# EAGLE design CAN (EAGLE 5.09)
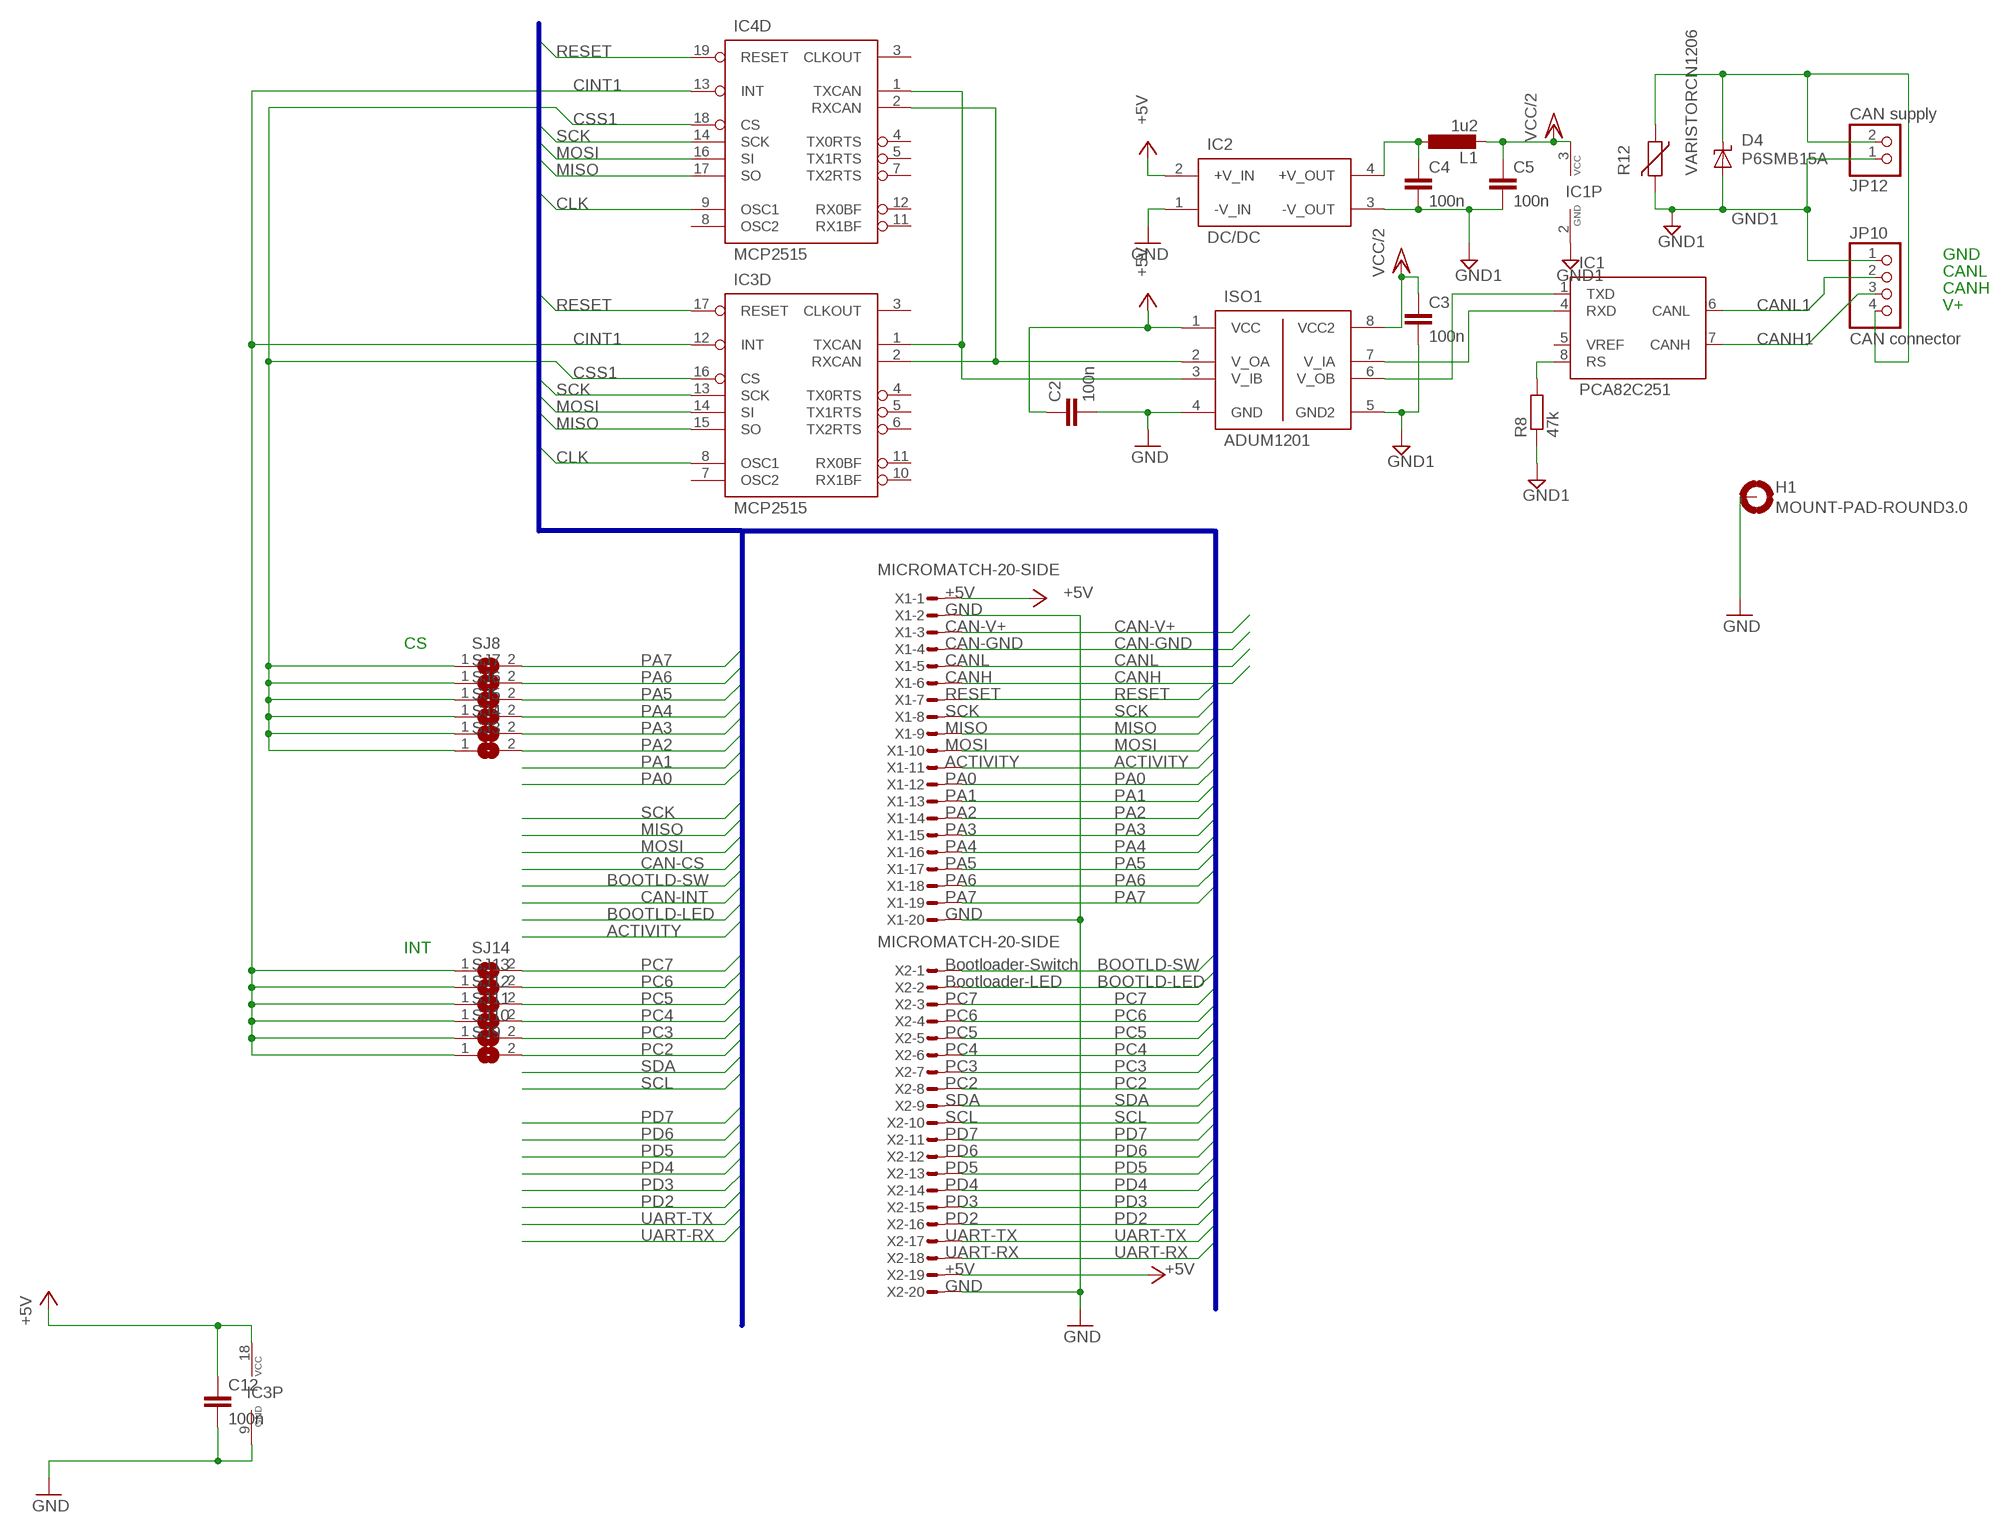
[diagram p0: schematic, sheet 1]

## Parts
C2  100n  C-EUC0805  [C0805]
C3  100n  C-EUC0805  [C0805]
C4  100n  C-EUC0805  [C0805]
C5  100n  C-EUC0805  [C0805]
C12  100n  C-EUC0805  [C0805]
D4  P6SMB15A  P6SMBXXA  [SMB]
H1  MOUNT-PAD-ROUND3.0  [3,0-PAD]
IC1  PCA82C251  PCA82C250  [DIL08]
IC2  DC/DC  [SIL4]
IC3  MCP2515  MCP2515SO  [SO-18W]
IC4  MCP2515  MCP2515ST  [TSSOP20]
ISO1  ADUM1201  [SO08]
JP10  CAN connector  PINHD-1X4  [1X04]
JP12  CAN supply  PINHD-1X2  [1X02]
L1  1u2  L-EUL3216C  [L3216C]
R8  47k  R-EU_R0805  [R0805]
R12  VARISTORCN1206  [CT/CN1206]
SJ3  SJ  [SJ]
SJ4  SJ  [SJ]
SJ5  SJ  [SJ]
SJ6  SJ  [SJ]
SJ7  SJ  [SJ]
SJ8  SJ  [SJ]
SJ9  SJ  [SJ]
SJ10  SJ  [SJ]
SJ11  SJ  [SJ]
SJ12  SJ  [SJ]
SJ13  SJ  [SJ]
SJ14  SJ  [SJ]
X1  MICROMATCH-20-SIDE  [MICROMATCH-20-SIDE]
X2  MICROMATCH-20-SIDE  [MICROMATCH-20-SIDE]

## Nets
+5V: C2.1 C12.1 IC2.2(+V_IN) IC3.18(P:VCC) ISO1.1(VCC) X1.1 X2.19
ACTIVITY: X1.11
BOOTLD-LED: X2.2
BOOTLD-SW: X2.1
CAN-GND [Power]: X1.4
CAN-V+ [Power]: X1.3
CAN_CONN_V+ [Power]: D4.C JP10.4 JP12.2 R12.1
CANH: X1.6
CANH1: IC1.7(CANH) JP10.3
CANH_TXD: IC3.1(D:TXCAN) IC4.1(D:TXCAN) ISO1.3(V_IB)
CANL: X1.5
CANL1: IC1.6(CANL) JP10.2
CANL_RXD: IC3.2(D:RXCAN) IC4.2(D:RXCAN) ISO1.2(V_OA)
CINT1: IC3.12(D:INT) IC4.13(D:INT) SJ9.1 SJ10.1 SJ11.1 SJ12.1 SJ13.1 SJ14.1
CLK: IC3.8(D:OSC1) IC4.9(D:OSC1)
CSS1: IC3.16(D:CS) IC4.18(D:CS) SJ3.1 SJ4.1 SJ5.1 SJ6.1 SJ7.1 SJ8.1
GND: C2.2 C12.2 H1.B3,0(MOUNT) IC2.1(-V_IN) IC3.9(P:GND) ISO1.4(GND) X1.2 X1.20 X2.20
GND1: C3.2 C4.2 C5.2 D4.A IC1.2(GND) IC2.3(-V_OUT) ISO1.5(GND2) JP10.1 JP12.1 R8.1 R12.2
MISO: IC3.15(D:SO) IC4.17(D:SO) X1.9
MOSI: IC3.14(D:SI) IC4.16(D:SI) X1.10
N$16: IC1.4(RXD) ISO1.7(V_IA)
N$17: IC1.1(TXD) ISO1.6(V_OB)
N$18: C4.1 IC2.4(+V_OUT) L1.1
N$19: IC1.8(RS) R8.2
PA0: X1.12
PA1: X1.13
PA2: SJ3.2 X1.14
PA3: SJ4.2 X1.15
PA4: SJ5.2 X1.16
PA5: SJ6.2 X1.17
PA6: SJ7.2 X1.18
PA7: SJ8.2 X1.19
PC2: SJ9.2 X2.8
PC3: SJ10.2 X2.7
PC4: SJ11.2 X2.6
PC5: SJ12.2 X2.5
PC6: SJ13.2 X2.4
PC7: SJ14.2 X2.3
PD2: X2.16
PD3: X2.15
PD4: X2.14
PD5: X2.13
PD6: X2.12
PD7: X2.11
RESET: IC3.17(D:RESET) IC4.19(D:RESET) X1.7
SCK: IC3.13(D:SCK) IC4.14(D:SCK) X1.8
SCL: X2.10
SDA: X2.9
UART-RX: X2.18
UART-TX: X2.17
VCC/2: C3.1 C5.1 IC1.3(VCC) ISO1.8(VCC2) L1.2
Unconnected: IC1.5(VREF) IC3.3(D:CLKOUT) IC3.4(D:TX0RTS) IC3.5(D:TX1RTS) IC3.6(D:TX2RTS) IC3.7(D:OSC2) IC3.10(D:RX1BF) IC3.11(D:RX0BF) IC4.3(D:CLKOUT) IC4.4(D:TX0RTS) IC4.5(D:TX1RTS) IC4.7(D:TX2RTS) IC4.8(D:OSC2) IC4.11(D:RX1BF) IC4.12(D:RX0BF)

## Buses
PA[0..7],PC[2..7],PD[2..7],SCK,MISO,MOSI,CAN-CS,BOOTLD-SW,CAN-INT,BOOTLD-LED,ACTIVITY,SDA,SCL,UART-RX,UART-TX,CLK,RESET

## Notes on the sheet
- GND
- CANL
- CANH
- V+
- +5V
- GND
- CAN-V+
- CS | CAN-GND
- CANL
- CANH
- RESET
- SCK
- MISO
- MOSI
- ACTIVITY
- PA0
- PA1
- PA2
- PA3
- PA4
- PA5
- PA6
- PA7
- GND
- INT
- Bootloader-Switch
- Bootloader-LED
- PC7
- PC6
- PC5
- PC4
- PC3
- PC2
- SDA
- SCL
- PD7
- PD6
- PD5
- PD4
- PD3
- PD2
- UART-TX
- UART-RX
- +5V
- GND

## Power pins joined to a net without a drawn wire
+5V: IC4.20(P:VCC)
GND: IC4.10(P:GND)

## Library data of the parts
C2-C5 C12 = rcl:C-EU: CAPACITOR, European symbol
D4 = 11my-ICs:P6SMBXXA: Suppressor diode
H1 = holes:MOUNT-PAD-ROUND: MOUNTING PAD, round
IC1 = 11my-CAN:PCA82C250: PCA82C250 CAN Bustreiber
IC2 = 11my-ICs:DC/DC
IC3 IC4 = 11my-CAN:MCP2515: MC2515 Stand-Alone CAN Controller With SPI Interface
ISO1 = 11my-ICs:ADUM1201: ADuM1201 Dual-Channel Digital Isolators zu beziehen per Sample oder bei Farnell
JP10 = pinhead:PINHD-1X4: PIN HEADER
JP12 = pinhead:PINHD-1X2: PIN HEADER
L1 = rcl:L-EU: INDUCTOR, European symbol
R8 = rcl:R-EU_: RESISTOR, European symbol
R12 = varistor:VARISTOR: VARISTOR
SJ3-SJ14 = jumper:SJ: SMD solder JUMPER
X1 X2 = apbteam_con-amp-micromatch:MICROMATCH-20: Micro-MaTch 20 Straight connector: Suited for both, female and male.

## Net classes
0 default: width 0.15 mm, clearance 0.3 mm
1 Power: width 0.5 mm, clearance 0.3 mm

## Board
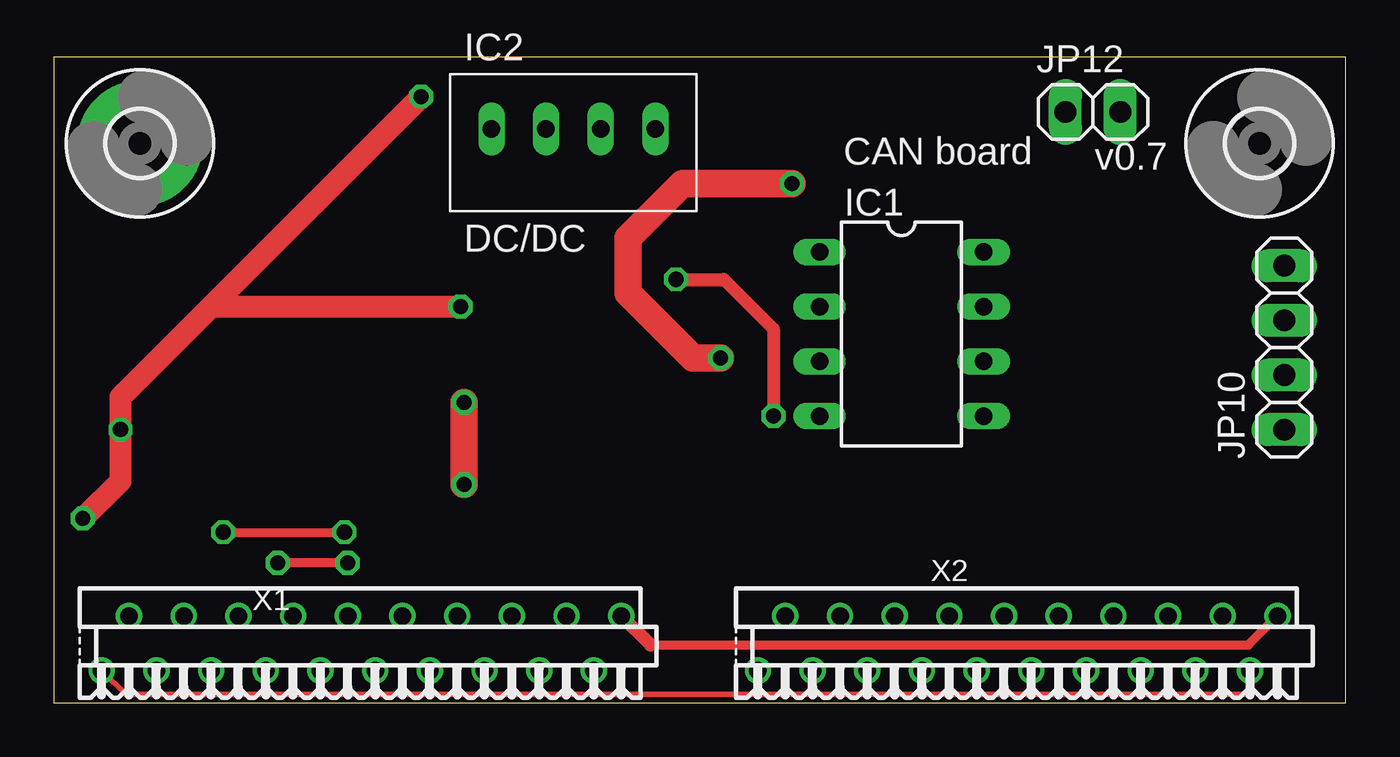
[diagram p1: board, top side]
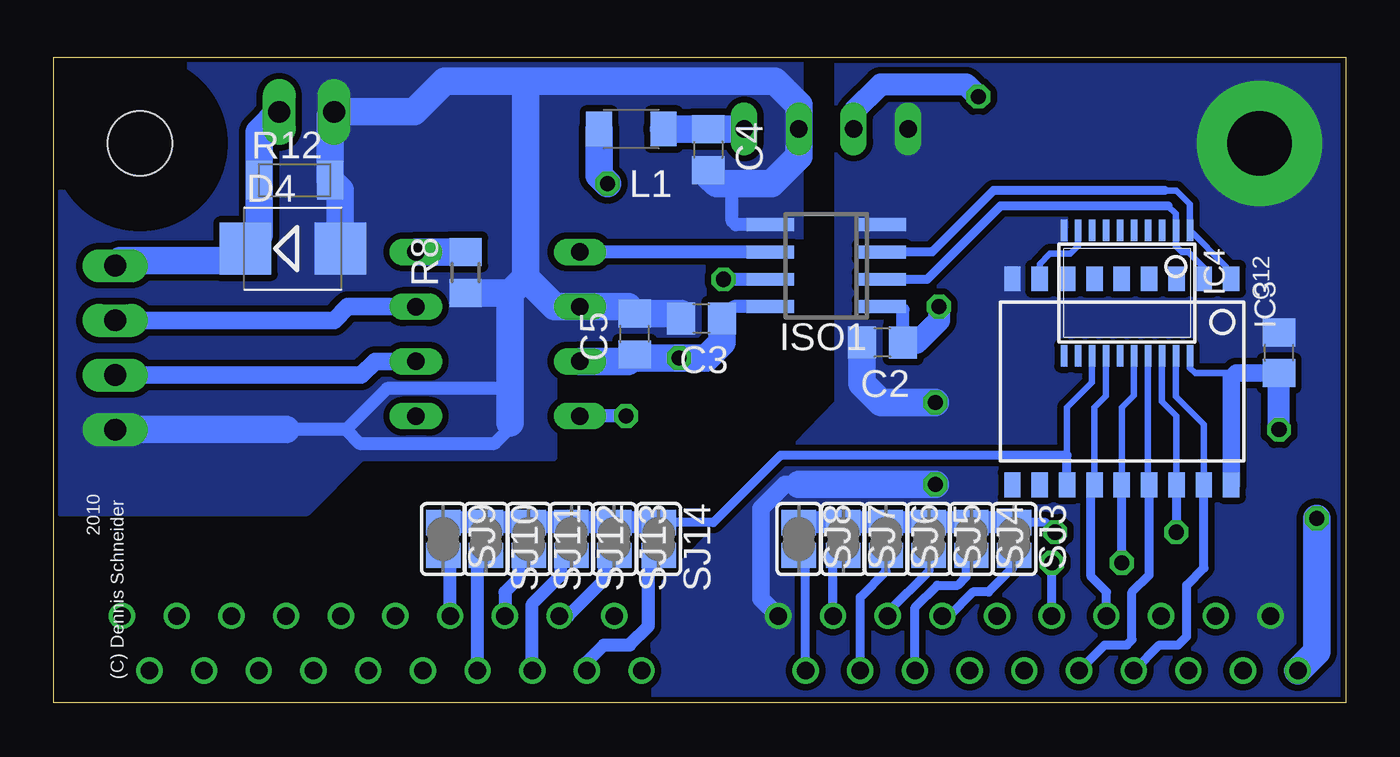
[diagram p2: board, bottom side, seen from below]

Size 60 x 30 mm. Coordinates in mm from the lower left corner, seen from the top.
Outline: 0,0 60,0 60,30 0,30 0,0
Copper layers (1+2*15+16): Top 0.035mm / dielectric 0.36mm / Route2 0.018mm / dielectric 0.71mm / Route15 0.018mm / dielectric 0.36mm / Bottom 0.035mm
Design rules "q-print.info *": minimum track width 6mil, minimum drill 0.3mm, track to track 6mil, track to pad 6mil, pad to pad 6mil, via to via 6mil, smd to smd 6mil, copper to edge 8mil, drill to drill 10mil, minimum pad ring 8mil, minimum via ring 8mil, stop-mask expansion 4mil, vias tented up to drill 16mil, thermal gap 10mil

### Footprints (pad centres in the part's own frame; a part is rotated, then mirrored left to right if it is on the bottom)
C0805 = smd 1.3 x 1.5: 1 -0.95,0; 2 0.95,0
SMB = smd 2.4 x 2.4: A 2.2,0; C -2.2,0
3,0-PAD = drill 3 pad 5.842 round: B3,0 0,0
DIL08 = drill 0.813 long: 1 -3.81,-3.81; 2 -1.27,-3.81; 3 1.27,-3.81; 4 3.81,-3.81; 5 3.81,3.81; 6 1.27,3.81; 7 -1.27,3.81; 8 -3.81,3.81
SIL4 = drill 0.813 long: 1 -3.81,0; 2 -1.27,0; 3 1.27,0; 4 3.81,0
SO-18W = smd 0.762 x 1.143: 1 -5.08,-4.788; 2 -3.81,-4.788; 3 -2.54,-4.788; 4 -1.27,-4.788; 5 0,-4.788; 6 1.27,-4.788; 7 2.54,-4.788; 8 3.81,-4.788; 9 5.08,-4.788; 10 5.08,4.788; 11 3.81,4.788; 12 2.54,4.788; 13 1.27,4.788; 14 0,4.788; 15 -1.27,4.788; 16 -2.54,4.788; 17 -3.81,4.788; 18 -5.08,4.788
TSSOP20 = smd 0.305 x 0.991: 1 -2.925,-2.918; 2 -2.275,-2.918; 3 -1.625,-2.918; 4 -0.975,-2.918; 5 -0.325,-2.918; 6 0.325,-2.918; 7 0.975,-2.918; 8 1.625,-2.918; 9 2.275,-2.918; 10 2.925,-2.918; 11 2.925,2.918; 12 2.275,2.918; 13 1.625,2.918; 14 0.975,2.918; 15 0.325,2.918; 16 -0.325,2.918; 17 -0.975,2.918; 18 -1.625,2.918; 19 -2.275,2.918; 20 -2.925,2.918
SO08 = smd 0.6 x 2.2: 1 -1.905,-2.6; 2 -0.635,-2.6; 3 0.635,-2.6; 4 1.905,-2.6; 5 1.905,2.6; 6 0.635,2.6; 7 -0.635,2.6; 8 -1.905,2.6
1X04 = drill 1.016 long: 1 -3.81,0; 2 -1.27,0; 3 1.27,0; 4 3.81,0
1X02 = drill 1.016 long: 1 -1.27,0; 2 1.27,0
L3216C = smd 1.2 x 1.6: 1 -1.5,0; 2 1.5,0
R0805 = smd 1.3 x 1.5: 1 -0.95,0; 2 0.95,0
CT/CN1206 = smd 1.2 x 1.8: 1 -1.65,0; 2 1.65,0
SJ = smd 1.168 x 1.6: 1 -0.762,0; 2 0.762,0
3,0 = hole 3: 0,0
MICROMATCH-20-SIDE = drill 0.813 round: 1 12.065,1.27; 2 10.795,-1.27; 3 9.525,1.27; 4 8.255,-1.27; 5 6.985,1.27; 6 5.715,-1.27; 7 4.445,1.27; 8 3.175,-1.27; 9 1.905,1.27; 10 0.635,-1.27; 11 -0.635,1.27; 12 -1.905,-1.27; 13 -3.175,1.27; 14 -4.445,-1.27; 15 -5.715,1.27; 16 -6.985,-1.27; 17 -8.255,1.27; 18 -9.525,-1.27; 19 -10.795,1.27; 20 -12.065,-1.27

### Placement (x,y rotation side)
C2  21.51,16.75 180 bottom
C3  29.92,17.86 180 bottom
C4  29.61,25.72 270 bottom
C5  33.02,17.14 90 bottom
C12  3.1,16.27 90 bottom
D4  48.89,21.11 0 bottom
H1  4,26 0 top
IC1  39.37,17.14 270 top
IC2  24.13,26.67 0 top
IC3  10.4,14.92 180 bottom
IC4  10.16,19.05 180 bottom
ISO1  24.13,20.32 90 bottom
JP10  57.15,16.51 90 top
JP12  48.26,27.46 0 top
L1  33.18,26.67 180 bottom
R8  40.88,20 90 bottom
R12  48.82,24.29 0 bottom
SJ3  15.4,7.62 270 bottom
SJ4  17.38,7.62 270 bottom
SJ5  19.37,7.62 270 bottom
SJ6  21.35,7.62 270 bottom
SJ7  23.34,7.62 270 bottom
SJ8  25.4,7.62 270 bottom
SJ9  41.91,7.62 270 bottom
SJ10  39.93,7.62 270 bottom
SJ11  37.94,7.62 270 bottom
SJ12  35.96,7.62 270 bottom
SJ13  33.97,7.62 270 bottom
SJ14  31.91,7.62 270 bottom
U$1  [3,0]  56,26 0 top
X1  14.29,2.78 180 top
X2  44.77,2.78 180 top

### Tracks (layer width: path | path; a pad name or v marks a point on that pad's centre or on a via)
+5V  (via drill 0.7)
  Top 0.254: X2.19 55.56,0.4 3.33,0.4 X1.1
  Top 1.016: v1.35,8.57 3.1,10.32 v3.1,12.7 3.1,14.21 7.14,18.26 7.3,18.41 | 7.3,18.41 v17.07,28.18 | 7.3,18.41 v18.89,18.41
  Bottom 0.305: IC4.20 7.24,15.57 6.99,15.32 5.08,15.32 C12.1
  Bottom 0.61: ISO1.1 20.72,18.41 20.56,18.26 C2.1
  Bottom 0.813: IC3.18 | IC3.18 5.32,15.08 5.08,15.32 3.18,15.32 3.17,15.32
  Bottom 1.016: v3.1,12.7 C12.1 | v17.07,28.18 17.62,28.73 21.59,28.73 22.86,27.46 IC2.2 | v18.89,18.41 18.89,17.78 19.92,16.75 C2.1 | C2.1
  Bottom 1.27: v1.35,8.57 1.35,2.38 X1.1
CAN_CONN_V+
  Bottom 1.27: JP12.2 50.47,26.53 R12.1 50.47,21.74 D4.C 51.65,20.56 56.91,20.56 JP10.4
CANH1
  Bottom 0.813: JP10.3 46.99,17.78 46.35,18.41 IC1.7
CANH_TXD
  Bottom 0.305: IC3.1 5.56,19.95 5.56,20.29 IC4.1 7.24,23.19 7.86,23.81 8.41,23.81
  Bottom 0.406: 8.41,23.81 16.35,23.81 19.21,20.95 ISO1.3
CANL1
  Bottom 0.813: JP10.2 45.72,15.24 45.09,15.88 IC1.6
CANL_RXD
  Bottom 0.305: 8.26,23.1 7.88,22.73 IC4.2 7.88,21.22 7.62,20.95 7.3,20.95 6.59,20.24 IC3.2 6.59,20.08
  Bottom 0.406: 8.26,23.1 16.03,23.1 19.45,19.68 ISO1.2
CINT1
  Bottom 0.305: IC4.13 11.79,14.88 12.94,13.73 IC3.12
  Bottom 0.406: IC3.12 | IC3.12 12.94,11.51 26.24,11.51 29.37,8.38 SJ14.1
  Bottom 1.016: SJ14.1 SJ13.1 | SJ13.1 | SJ13.1 SJ12.1 | SJ12.1 | SJ12.1 SJ11.1 SJ10.1 SJ9.1
CLK
  Bottom 0.305: IC4.9 12.44,21.22 12.78,20.88 13.73,20.88 14.21,20.4 IC3.8
CSS1  (via drill 0.7)
  Top 0.406: v7.86,7.94 v13.49,7.94
  Bottom 0.305: IC3.16 7.86,13.34 8.54,14.01 IC4.18
  Bottom 0.406: IC3.16 v7.86,7.94 | v13.49,7.94 13.94,8.38 SJ3.1
  Bottom 1.016: SJ3.1 SJ4.1 SJ5.1 SJ6.1 SJ7.1 SJ8.1
GND  (via drill 0.7)
  Top 0.406: 27.7,2.7 55.48,2.7 X2.20
  Top 0.61: X1.20 27.7,2.7
  Top 1.27: v19.05,10.16 v19.05,13.97
  Bottom 0.813: 25.4,10.16 26.04,10.16 27.15,9.05 27.15,4.84 X1.20
  Bottom 1.27: 25.4,10.16 v19.05,10.16 | v19.05,13.97 21.59,13.97 22.46,14.84 C2.2
  pour Bottom (isolate 0.254, rank 5, no thermals): 0,0 32.14,0 32.22,5.08 23.65,13.97 23.65,30 0,30
GND1
  Bottom 0.61: ISO1.5 28.34,22.23 28.5,22.38 28.5,24.13 | 46.43,12.7 49.21,12.7 | 46.43,12.7 44.53,14.61 38.82,14.61 | 46.43,12.7 45.8,12.06 39.53,12.06 38.73,12.86
  Bottom 1.27: C4.2 29.61,24.53 29.21,24.13 28.5,24.13 26.67,24.13 25.4,25.4 IC2.3 25.4,27.78 26.51,28.89 38.1,28.89 | 49.21,12.7 JP10.1 | 38.1,28.89 41.85,28.89 43.28,27.46 JP12.1 47.17,27.29 R12.2 46.7,23.82 D4.A 46.61,21.2 | 38.1,28.89 38.1,19.77 | C3.2 30.87,18.09 C5.2 33.34,18.41 IC1.2 36.75,18.41 38.1,19.77 | 38.82,19.05 R8.1 | 38.1,19.77 38.82,19.05 | 38.82,19.05 38.82,14.61 38.82,13.02 38.81,13.02
  pour Bottom (no thermals): 25.4,30.48 25.4,16.51 36.83,16.51 36.83,11.43 45.72,11.43 48.26,8.89 59.69,8.89 59.69,30.48
MISO
  Bottom 0.305: IC4.17 9.19,10.19 IC3.15
  Bottom 0.406: IC3.15 9.13,5.95 9.92,5.16 9.92,2.94 10.16,2.7 11.19,2.7 X1.9
MOSI  (via drill 0.7)
  Top 0.406: v13.65,6.51 v10.4,6.51 | v10.4,6.51
  Bottom 0.305: IC4.16 9.84,14.29 10.4,13.73 IC3.14
  Bottom 0.406: IC3.14 v10.4,6.51 | X1.10 v13.65,6.51
N$16  (via drill 0.7)
  Top 0.61: v33.42,13.34 33.42,17.38 31.11,19.68 v28.89,19.68
  Bottom 0.61: ISO1.7 v28.89,19.68 | v33.42,13.34 IC1.4
N$17
  Bottom 0.61: ISO1.6 IC1.1
N$18
  Bottom 1.27: IC2.4 C4.1 L1.1
N$19
  Bottom 1.27: IC1.8 R8.2
PA2
  Bottom 0.406: X1.14 18.41,4.05 17.3,5.16 16.59,5.16 15.48,6.27 15.48,6.78 SJ3.2
PA3
  Bottom 0.406: X1.15 20,4.45 18.97,5.48 18.02,5.48 17.62,5.87 17.62,6.62 SJ4.2
PA4
  Bottom 0.406: SJ5.2 19.37,6.11 21.27,4.21 X1.16
PA5
  Bottom 0.406: X1.17 22.54,4.92 21.35,6.11 SJ6.2
PA6
  Bottom 0.406: SJ7.2 23.81,6.38 X1.18
PA7
  Bottom 0.406: SJ8.2 25.08,6.54 X1.19
PC2
  Bottom 0.61: SJ9.2 41.59,6.54 X2.8
PC3
  Bottom 0.406: 40.01,6.78 SJ10.2
  Bottom 0.61: 40.01,6.78 40.32,6.46 X2.7
PC4
  Bottom 0.61: SJ11.2 38.42,6.38 38.42,5.79 39.05,5.16 X2.6
PC5
  Bottom 0.61: SJ12.2 36.43,6.38 36.43,5.95 37.78,4.6 X2.5
PC6
  Bottom 0.61: SJ13.2 34.45,6.38 34.45,5.71 36.12,4.05 X2.4
PC7
  Bottom 0.61: SJ14.2 32.38,6.38 32.38,3.57 33.26,2.7 34.45,2.7 35.24,1.91 X2.3
RESET
  Bottom 0.305: IC3.17 6.59,12.94 7.88,14.23 IC4.19
  Bottom 0.406: IC3.17 6.59,6.27 7.38,5.48 7.38,3.1 7.78,2.7 8.65,2.7 X1.7
SCK
  Bottom 0.305: IC4.14 11.13,14.27 11.67,13.73 IC3.13
  Bottom 0.406: IC3.13 11.83,9.98 11.83,5.87 11.11,5.16 X1.8
VCC/2  (via drill 0.7)
  Top 1.27: v34.29,24.13 29.21,24.13 26.67,21.59 26.67,19.05 29.69,16.03 v30.96,16.03
  Bottom 0.61: ISO1.8 28.42,18.41 C3.1
  Bottom 1.27: IC1.3 33.34,15.88 C5.1 32.86,16.03 v30.96,16.03 29.69,16.03 28.97,16.75 C3.1 | v34.29,24.13 34.68,24.52 L1.2

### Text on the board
tPlace: CAN board
bPlace: 2010 | (C) Dennis Schneider
tNames: v0.7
